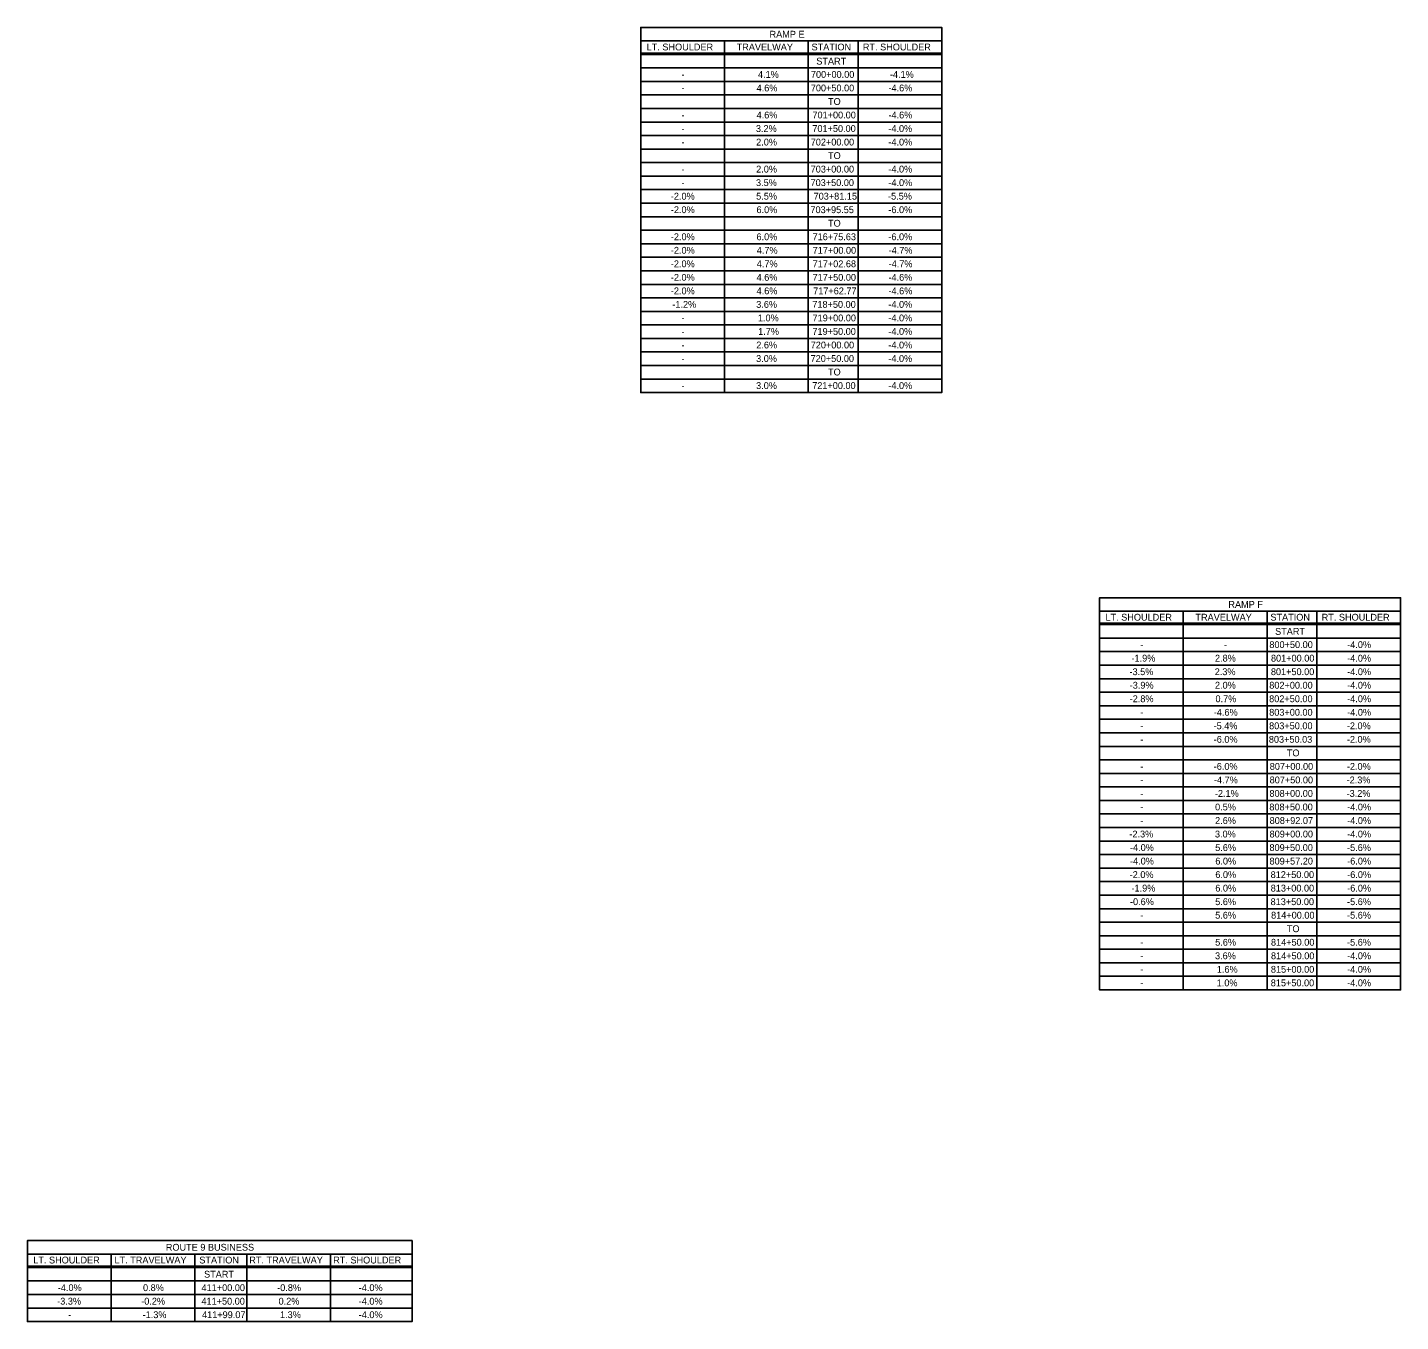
# Model space of a CAD drawing. Extents: x -15319374 to 1762012, y 465773 to 3693661.
# Drawn here: x -15316467 to -15315864, y 3691054 to 3691623 of the extents above; entities that cross this region are included whole.
import ezdxf

# ---------------------------------------------------------------- set-up
doc = ezdxf.new("R2010")
doc.units = 0
doc.layers.add('BORDER', color=7, linetype='Continuous')
doc.layers.add('DIMENSIONS', color=7, linetype='Continuous')

msp = doc.modelspace()

# ---------------------------------------------------------------- linework, layer by layer
at = {"layer": 'BORDER'}
for p, q in [((-15316197.39, 3691616.67), (-15316197.39, 3691498.47)), ((-15316160.62, 3691616.67), (-15316160.62, 3691462.23)), ((-15316123.85, 3691616.67), (-15316123.85, 3691462.23)), ((-15316101.98, 3691616.67), (-15316101.98, 3691462.23)), ((-15316197.39, 3691611.39), (-15316065.21, 3691611.39)), ((-15316197.39, 3691610.79), (-15316065.21, 3691610.79)), ((-15316197.39, 3691604.85), (-15316065.21, 3691604.85)), ((-15316197.39, 3691604.85), (-15316065.21, 3691604.85)), ((-15316197.39, 3691604.85), (-15316065.21, 3691604.85)), ((-15316197.39, 3691598.91), (-15316065.21, 3691598.91)), ((-15316197.39, 3691592.97), (-15316065.21, 3691592.97)), ((-15316197.39, 3691587.02), (-15316065.21, 3691587.02)), ((-15316197.39, 3691581.08), (-15316065.21, 3691581.08)), ((-15316197.39, 3691575.14), (-15316065.21, 3691575.14)), ((-15316197.39, 3691569.19), (-15316065.21, 3691569.19)), ((-15316197.39, 3691563.25), (-15316065.21, 3691563.25)), ((-15316197.39, 3691557.31), (-15316065.21, 3691557.31)), ((-15316197.39, 3691551.37), (-15316065.21, 3691551.37)), ((-15316197.39, 3691545.42), (-15316065.21, 3691545.42)), ((-15316197.39, 3691539.48), (-15316065.21, 3691539.48)), ((-15316197.39, 3691533.54), (-15316065.21, 3691533.54)), ((-15316197.39, 3691527.6), (-15316065.21, 3691527.6)), ((-15316197.39, 3691521.65), (-15316065.21, 3691521.65)), ((-15316197.39, 3691515.71), (-15316065.21, 3691515.71)), ((-15316197.39, 3691509.77), (-15316065.21, 3691509.77)), ((-15316197.39, 3691503.82), (-15316065.21, 3691503.82)), ((-15316197.39, 3691497.88), (-15316065.21, 3691497.88)), ((-15316197.39, 3691491.94), (-15316065.21, 3691491.94)), ((-15316197.39, 3691486), (-15316065.21, 3691486)), ((-15316197.39, 3691480.05), (-15316065.21, 3691480.05)), ((-15316197.39, 3691474.11), (-15316065.21, 3691474.11)), ((-15316197.39, 3691468.17), (-15316065.21, 3691468.17)), ((-15315995.84, 3691366.18), (-15315995.84, 3691247.98)), ((-15315959.08, 3691366.18), (-15315959.08, 3691199.85)), ((-15315922.31, 3691366.18), (-15315922.31, 3691199.85)), ((-15315900.43, 3691366.18), (-15315900.43, 3691199.85)), ((-15315995.84, 3691360.9), (-15315863.66, 3691360.9)), ((-15315995.84, 3691360.3), (-15315863.66, 3691360.3)), ((-15315995.84, 3691354.36), (-15315863.66, 3691354.36)), ((-15315995.84, 3691354.36), (-15315863.66, 3691354.36)), ((-15315995.84, 3691354.36), (-15315863.66, 3691354.36)), ((-15315995.84, 3691348.42), (-15315863.66, 3691348.42)), ((-15315995.84, 3691342.47), (-15315863.66, 3691342.47)), ((-15315995.84, 3691336.53), (-15315863.66, 3691336.53)), ((-15315995.84, 3691330.59), (-15315863.66, 3691330.59)), ((-15315995.84, 3691324.64), (-15315863.66, 3691324.64)), ((-15315995.84, 3691318.7), (-15315863.66, 3691318.7)), ((-15315995.84, 3691312.76), (-15315863.66, 3691312.76)), ((-15315995.84, 3691306.82), (-15315863.66, 3691306.82)), ((-15315995.84, 3691300.87), (-15315863.66, 3691300.87)), ((-15315995.84, 3691294.93), (-15315863.66, 3691294.93)), ((-15315995.84, 3691288.99), (-15315863.66, 3691288.99)), ((-15315995.84, 3691283.05), (-15315863.66, 3691283.05)), ((-15315995.84, 3691277.1), (-15315863.66, 3691277.1)), ((-15315995.84, 3691271.16), (-15315863.66, 3691271.16)), ((-15315995.84, 3691265.22), (-15315863.66, 3691265.22)), ((-15315995.84, 3691259.28), (-15315863.66, 3691259.28)), ((-15315995.84, 3691253.33), (-15315863.66, 3691253.33)), ((-15315995.84, 3691247.39), (-15315863.66, 3691247.39)), ((-15315995.84, 3691241.45), (-15315863.66, 3691241.45)), ((-15315995.84, 3691235.5), (-15315863.66, 3691235.5)), ((-15315995.84, 3691229.56), (-15315863.66, 3691229.56)), ((-15315995.84, 3691223.62), (-15315863.66, 3691223.62)), ((-15315995.84, 3691217.68), (-15315863.66, 3691217.68)), ((-15315995.84, 3691211.73), (-15315863.66, 3691211.73)), ((-15315995.84, 3691205.79), (-15315863.66, 3691205.79)), ((-15316430.05, 3691083.79), (-15316430.05, 3691054.14)), ((-15316393.29, 3691083.79), (-15316393.29, 3691054.14)), ((-15316370.41, 3691083.79), (-15316370.41, 3691054.14)), ((-15316333.64, 3691083.79), (-15316333.64, 3691054.14)), ((-15316333.64, 3691083.79), (-15316333.64, 3691054.14)), ((-15316466.82, 3691078.51), (-15316297.88, 3691078.51)), ((-15316466.82, 3691077.91), (-15316297.88, 3691077.91)), ((-15316466.82, 3691071.97), (-15316297.88, 3691071.97)), ((-15316466.82, 3691071.97), (-15316297.88, 3691071.97)), ((-15316466.82, 3691071.97), (-15316297.88, 3691071.97)), ((-15316466.82, 3691066.02), (-15316297.88, 3691066.02)), ((-15316466.82, 3691060.08), (-15316297.88, 3691060.08))]:
    msp.add_line(p, q, dxfattribs=at)
for points in [[(-15316197.39, 3691616.67), (-15316197.39, 3691622.61), (-15316065.21, 3691622.61), (-15316065.21, 3691616.67)], [(-15315995.84, 3691366.18), (-15315995.84, 3691372.12), (-15315863.66, 3691372.12), (-15315863.66, 3691366.18)], [(-15316466.82, 3691083.79), (-15316466.82, 3691089.73), (-15316297.88, 3691089.73), (-15316297.88, 3691083.79)]]:
    msp.add_lwpolyline(points, dxfattribs=at)
for points in [[(-15316197.39, 3691616.67), (-15316065.21, 3691616.67), (-15316065.21, 3691462.23), (-15316197.39, 3691462.23)], [(-15315995.84, 3691366.18), (-15315863.66, 3691366.18), (-15315863.66, 3691199.85), (-15315995.84, 3691199.85)], [(-15316466.82, 3691083.79), (-15316297.88, 3691083.79), (-15316297.88, 3691054.14), (-15316466.82, 3691054.14)]]:
    msp.add_lwpolyline(points, close=True, dxfattribs=at)

# ---------------------------------------------------------------- texts
at = {"layer": 'DIMENSIONS'}
for s, p in [('RAMP E', (-15316140.84, 3691618.14)), ('LT. SHOULDER', (-15316194.83, 3691612.53)), ('TRAVELWAY', (-15316155.3, 3691612.53)), ('STATION', (-15316122.39, 3691612.53)), ('RT. SHOULDER', (-15316099.85, 3691612.53)), ('START', (-15316120.31, 3691606.31)), ('-', (-15316179.51, 3691600.48)), ('4.1%', (-15316145.92, 3691600.48)), ('700+00.00', (-15316122.67, 3691600.48)), ('-4.1%', (-15316087.98, 3691600.48)), ('-', (-15316179.51, 3691594.53)), ('4.6%', (-15316146.53, 3691594.53)), ('700+50.00', (-15316122.72, 3691594.53)), ('-4.6%', (-15316088.6, 3691594.53)), ('TO', (-15316115.16, 3691588.59)), ('-', (-15316179.51, 3691582.65)), ('4.6%', (-15316146.53, 3691582.65)), ('701+00.00', (-15316122.01, 3691582.65)), ('-4.6%', (-15316088.6, 3691582.65)), ('-', (-15316179.51, 3691576.71)), ('3.2%', (-15316146.84, 3691576.71)), ('701+50.00', (-15316122.05, 3691576.71)), ('-4.0%', (-15316088.65, 3691576.71)), ('-', (-15316179.51, 3691570.76)), ('2.0%', (-15316146.72, 3691570.76)), ('702+00.00', (-15316122.76, 3691570.76)), ('-4.0%', (-15316088.65, 3691570.76)), ('TO', (-15316115.16, 3691564.82)), ('-', (-15316179.51, 3691558.88)), ('2.0%', (-15316146.72, 3691558.88)), ('703+00.00', (-15316122.79, 3691558.88)), ('-4.0%', (-15316088.65, 3691558.88)), ('-', (-15316179.51, 3691552.94)), ('3.5%', (-15316146.79, 3691552.94)), ('703+50.00', (-15316122.83, 3691552.94)), ('-4.0%', (-15316088.65, 3691552.94)), ('-2.0%', (-15316184.2, 3691546.99)), ('5.5%', (-15316146.72, 3691546.99)), ('703+81.15', (-15316121.5, 3691546.99)), ('-5.5%', (-15316088.79, 3691546.99)), ('-2.0%', (-15316184.2, 3691541.05)), ('6.0%', (-15316146.58, 3691541.05)), ('703+95.55', (-15316122.87, 3691541.05)), ('-6.0%', (-15316088.65, 3691541.05)), ('TO', (-15316115.16, 3691535.11)), ('-2.0%', (-15316184.2, 3691529.16)), ('6.0%', (-15316146.58, 3691529.16)), ('716+75.63', (-15316121.95, 3691529.16)), ('-6.0%', (-15316088.65, 3691529.16)), ('-2.0%', (-15316184.2, 3691523.22)), ('4.7%', (-15316146.46, 3691523.22)), ('717+00.00', (-15316121.89, 3691523.22)), ('-4.7%', (-15316088.53, 3691523.22)), ('-2.0%', (-15316184.2, 3691517.28)), ('4.7%', (-15316146.46, 3691517.28)), ('717+02.68', (-15316121.92, 3691517.28)), ('-4.7%', (-15316088.53, 3691517.28)), ('-2.0%', (-15316184.2, 3691511.34)), ('4.6%', (-15316146.53, 3691511.34)), ('717+50.00', (-15316121.94, 3691511.34)), ('-4.6%', (-15316088.6, 3691511.34)), ('-2.0%', (-15316184.2, 3691505.39)), ('4.6%', (-15316146.53, 3691505.39)), ('717+62.77', (-15316121.7, 3691505.39)), ('-4.6%', (-15316088.6, 3691505.39)), ('-1.2%', (-15316183.54, 3691499.45)), ('3.6%', (-15316146.7, 3691499.45)), ('718+50.00', (-15316122.05, 3691499.45)), ('-4.0%', (-15316088.65, 3691499.45)), ('-', (-15316179.51, 3691493.51)), ('1.0%', (-15316145.97, 3691493.51)), ('719+00.00', (-15316121.96, 3691493.51)), ('-4.0%', (-15316088.65, 3691493.51)), ('-', (-15316179.51, 3691487.57)), ('1.7%', (-15316145.85, 3691487.57)), ('719+50.00', (-15316122.01, 3691487.57)), ('-4.0%', (-15316088.65, 3691487.57)), ('-', (-15316179.51, 3691481.62)), ('2.6%', (-15316146.68, 3691481.62)), ('720+00.00', (-15316122.76, 3691481.62)), ('-4.0%', (-15316088.65, 3691481.62)), ('-', (-15316179.51, 3691475.68)), ('3.0%', (-15316146.75, 3691475.68)), ('720+50.00', (-15316122.81, 3691475.68)), ('-4.0%', (-15316088.65, 3691475.68)), ('TO', (-15316115.16, 3691469.74)), ('-', (-15316179.51, 3691463.8)), ('3.0%', (-15316146.75, 3691463.8)), ('721+00.00', (-15316122.1, 3691463.8)), ('-4.0%', (-15316088.65, 3691463.8)), ('RAMP F', (-15315939.29, 3691367.65)), ('LT. SHOULDER', (-15315993.29, 3691362.04)), ('TRAVELWAY', (-15315953.75, 3691362.04)), ('STATION', (-15315920.84, 3691362.04)), ('RT. SHOULDER', (-15315898.31, 3691362.04)), ('START', (-15315918.77, 3691355.81)), ('-', (-15315977.97, 3691349.99)), ('-', (-15315941.2, 3691349.99)), ('800+50.00', (-15315921.29, 3691349.99)), ('-4.0%', (-15315887.1, 3691349.99)), ('-1.9%', (-15315981.85, 3691344.04)), ('2.8%', (-15315945.18, 3691344.04)), ('801+00.00', (-15315920.58, 3691344.04)), ('-4.0%', (-15315887.1, 3691344.04)), ('-3.5%', (-15315982.72, 3691338.1)), ('2.3%', (-15315945.29, 3691338.1)), ('801+50.00', (-15315920.62, 3691338.1)), ('-4.0%', (-15315887.1, 3691338.1)), ('-3.9%', (-15315982.63, 3691332.16)), ('2.0%', (-15315945.18, 3691332.16)), ('802+00.00', (-15315921.33, 3691332.16)), ('-4.0%', (-15315887.1, 3691332.16)), ('-2.8%', (-15315982.65, 3691326.21)), ('0.7%', (-15315944.96, 3691326.21)), ('802+50.00', (-15315921.38, 3691326.21)), ('-4.0%', (-15315887.1, 3691326.21)), ('-', (-15315977.97, 3691320.27)), ('-4.6%', (-15315945.7, 3691320.27)), ('803+00.00', (-15315921.36, 3691320.27)), ('-4.0%', (-15315887.1, 3691320.27)), ('-', (-15315977.97, 3691314.33)), ('-5.4%', (-15315945.79, 3691314.33)), ('803+50.00', (-15315921.4, 3691314.33)), ('-2.0%', (-15315887.24, 3691314.33)), ('-', (-15315977.97, 3691308.39)), ('-6.0%', (-15315945.74, 3691308.39)), ('803+50.03', (-15315921.51, 3691308.39)), ('TO', (-15315913.61, 3691302.44)), ('-2.0%', (-15315887.24, 3691308.39)), ('-6.0%', (-15315945.74, 3691296.5)), ('807+00.00', (-15315921.12, 3691296.5)), ('-2.0%', (-15315887.24, 3691296.5)), ('-', (-15315977.97, 3691296.5)), ('-4.7%', (-15315945.63, 3691290.56)), ('807+50.00', (-15315921.17, 3691290.56)), ('-2.3%', (-15315887.36, 3691290.56)), ('-', (-15315977.97, 3691290.56)), ('-2.1%', (-15315945.22, 3691284.62)), ('808+00.00', (-15315921.24, 3691284.62)), ('-3.2%', (-15315887.36, 3691284.62)), ('-', (-15315977.97, 3691284.62)), ('0.5%', (-15315945.13, 3691278.67)), ('808+50.00', (-15315921.29, 3691278.67)), ('-4.0%', (-15315887.1, 3691278.67)), ('-', (-15315977.97, 3691278.67)), ('2.6%', (-15315945.13, 3691272.73)), ('808+92.07', (-15315921.17, 3691272.73)), ('-4.0%', (-15315887.1, 3691272.73)), ('-2.3%', (-15315982.77, 3691266.79)), ('-', (-15315977.97, 3691272.73)), ('3.0%', (-15315945.2, 3691266.79)), ('809+00.00', (-15315921.19, 3691266.79)), ('-4.0%', (-15315887.1, 3691266.79)), ('-4.0%', (-15315982.51, 3691260.84)), ('5.6%', (-15315945.08, 3691260.84)), ('809+50.00', (-15315921.24, 3691260.84)), ('-5.6%', (-15315887.15, 3691260.84)), ('-4.0%', (-15315982.51, 3691254.9)), ('6.0%', (-15315945.03, 3691254.9)), ('809+57.20', (-15315921.22, 3691254.9)), ('-6.0%', (-15315887.1, 3691254.9)), ('-2.0%', (-15315982.65, 3691248.96)), ('6.0%', (-15315945.03, 3691248.96)), ('812+50.00', (-15315920.72, 3691248.96)), ('-6.0%', (-15315887.1, 3691248.96)), ('-1.9%', (-15315981.85, 3691243.02)), ('6.0%', (-15315945.03, 3691243.02)), ('813+00.00', (-15315920.7, 3691243.02)), ('-6.0%', (-15315887.1, 3691243.02)), ('-0.6%', (-15315982.51, 3691237.07)), ('5.6%', (-15315945.08, 3691237.07)), ('813+50.00', (-15315920.74, 3691237.07)), ('-5.6%', (-15315887.15, 3691237.07)), ('5.6%', (-15315945.08, 3691231.13)), ('814+00.00', (-15315920.53, 3691231.13)), ('-5.6%', (-15315887.15, 3691231.13)), ('-', (-15315977.97, 3691231.13)), ('TO', (-15315913.61, 3691225.19)), ('5.6%', (-15315945.08, 3691219.25)), ('814+50.00', (-15315920.58, 3691219.25)), ('-5.6%', (-15315887.15, 3691219.25)), ('-', (-15315977.97, 3691219.25)), ('3.6%', (-15315945.15, 3691213.3)), ('814+50.00', (-15315920.58, 3691213.3)), ('-4.0%', (-15315887.1, 3691213.3)), ('-', (-15315977.97, 3691213.3)), ('1.6%', (-15315944.37, 3691207.36)), ('815+00.00', (-15315920.62, 3691207.36)), ('-4.0%', (-15315887.1, 3691207.36)), ('-', (-15315977.97, 3691207.36)), ('1.0%', (-15315944.42, 3691201.42)), ('815+50.00', (-15315920.67, 3691201.42)), ('-4.0%', (-15315887.1, 3691201.42)), ('-', (-15315977.97, 3691201.42)), ('LT. SHOULDER', (-15316464.27, 3691079.65)), ('LT. TRAVELWAY', (-15316428.6, 3691079.65)), ('ROUTE 9 BUSINESS', (-15316406.04, 3691085.26)), ('STATION', (-15316391.32, 3691079.65)), ('RT. TRAVELWAY', (-15316369.39, 3691079.65)), ('RT. SHOULDER', (-15316332.52, 3691079.65)), ('START', (-15316389.25, 3691073.42)), ('-4.0%', (-15316453.49, 3691067.51)), ('0.8%', (-15316416.06, 3691067.51)), ('411+00.00', (-15316390.35, 3691067.51)), ('-0.8%', (-15316357.13, 3691067.51)), ('-4.0%', (-15316321.31, 3691067.51)), ('-3.3%', (-15316453.77, 3691061.57)), ('-0.2%', (-15316416.86, 3691061.57)), ('411+50.00', (-15316390.4, 3691061.57)), ('0.2%', (-15316356.51, 3691061.57)), ('-4.0%', (-15316321.31, 3691061.57)), ('-1.3%', (-15316416.23, 3691055.63)), ('411+99.07', (-15316390.13, 3691055.63)), ('1.3%', (-15316355.88, 3691055.63)), ('-4.0%', (-15316321.31, 3691055.63)), ('-', (-15316448.95, 3691055.63))]:
    msp.add_text(s, height=3, dxfattribs=at).set_placement(p)

doc.saveas('drawing.dxf')
